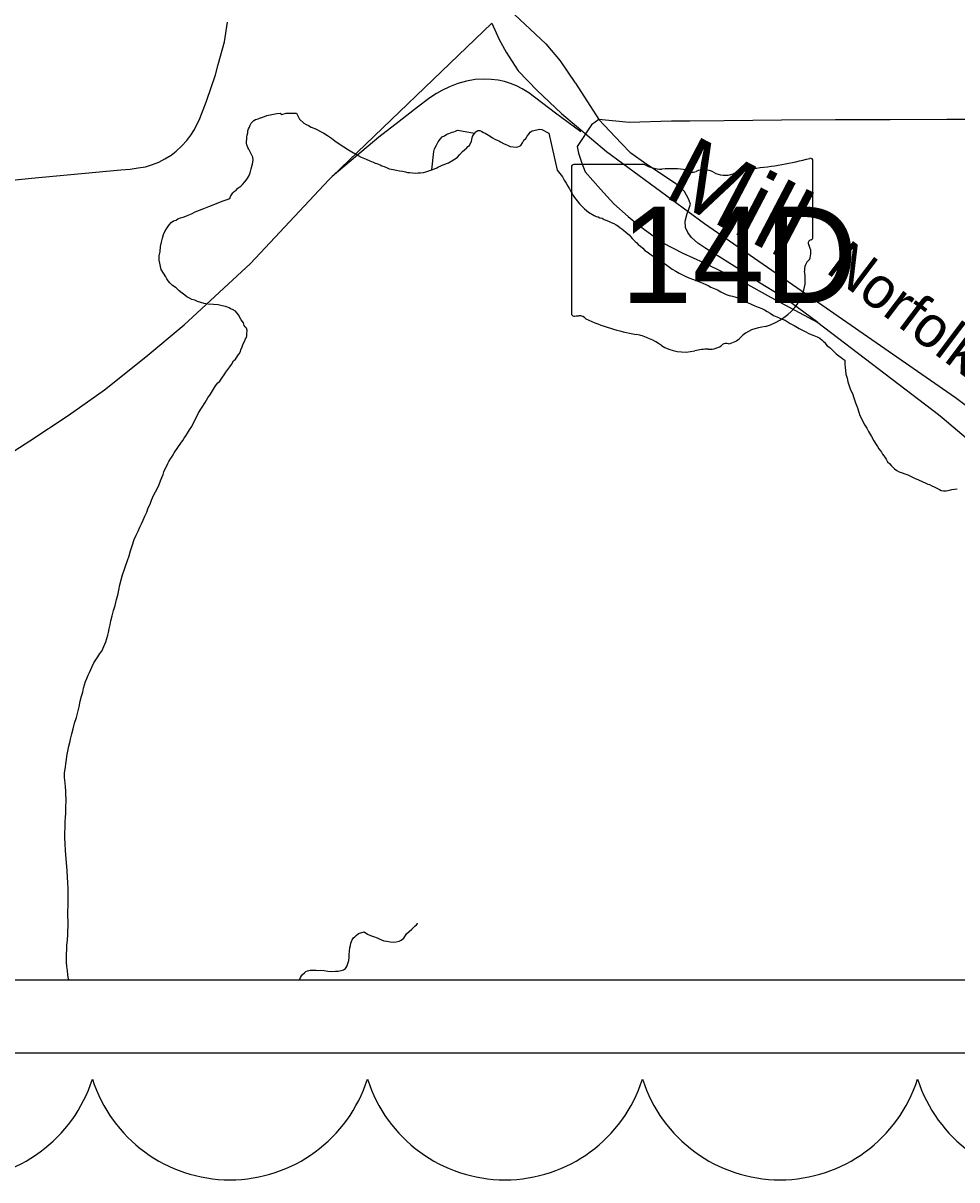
# Model space of a CAD drawing. Extents: x 0 to 96.2, y -27.5 to 31.3.
# Drawn here: x 48.919 to 50.194, y 13.714 to 15.293 of the extents above; entities that cross this region are included whole.
import ezdxf

# ---------------------------------------------------------------- set-up
doc = ezdxf.new("R2010")
doc.units = 0
for name, color, linetype in [('BOTTOM-BLKS', 7, 'Continuous'), ('TB1', 7, 'Continuous'), ('TB_BORDER', 7, 'Continuous'), ('TB_DUAL_PROF', 7, 'Continuous'), ('TB_PP_50x10_GRID', 7, 'Continuous'), ('TB_PROF_20x5', 7, 'Continuous'), ('TB_PROF_30x10', 7, 'Continuous'), ('TB_PSDSOD', 7, 'Continuous'), ('TB_SUPER_50x1_GRID', 7, 'Continuous')]:
    doc.layers.add(name, color=color, linetype=linetype)

msp = doc.modelspace()

# ---------------------------------------------------------------- linework, layer by layer
at = {"layer": 'BOTTOM-BLKS'}
msp.add_lwpolyline([(43.8234, 18.3711), (43.8234, 13.9869), (50.6234, 13.9869), (50.6234, 20.7869), (47.5697, 20.7869)], dxfattribs=at)
at = {"layer": 'TB1'}
for p, q in [((43.8234, 13.9869), (50.6234, 13.9869)), ((43.7234, 13.8869), (50.7234, 13.8869))]:
    msp.add_line(p, q, dxfattribs=at)
at = {"layer": 'TB_BORDER'}
for points in [[(49.1067, 14.9878), (49.1081, 14.9939), (49.1092, 14.9992), (49.1107, 15.0042), (49.1125, 15.0084), (49.1147, 15.0122), (49.1166, 15.0149), (49.1188, 15.0179), (49.1214, 15.0206), (49.1244, 15.0229), (49.1278, 15.0241), (49.1305, 15.0257), (49.1339, 15.0272), (49.1377, 15.028), (49.1411, 15.0292), (49.1445, 15.0308), (49.149, 15.0327), (49.1539, 15.0351), (49.1599, 15.0374), (49.166, 15.0398), (49.1728, 15.0425), (49.183, 15.0468), (49.1909, 15.05), (49.1977, 15.0523), (49.2011, 15.0535), (49.2022, 15.0562), (49.2037, 15.0585), (49.2052, 15.0612), (49.2074, 15.0631), (49.2101, 15.065), (49.2123, 15.0677), (49.2161, 15.0704), (49.2187, 15.0727), (49.2217, 15.0762), (49.225, 15.0804), (49.2273, 15.0839), (49.2291, 15.0884), (49.2305, 15.0938), (49.232, 15.1006), (49.233, 15.106), (49.2326, 15.1098), (49.2314, 15.1124), (49.2271, 15.1207), (49.226, 15.123), (49.2244, 15.1268), (49.224, 15.129), (49.2239, 15.1313), (49.2243, 15.1344), (49.2246, 15.1374), (49.225, 15.1401), (49.2257, 15.1431), (49.226, 15.1458), (49.2267, 15.1485), (49.2279, 15.1507), (49.229, 15.1534), (49.2304, 15.1561), (49.2323, 15.158), (49.2342, 15.1599), (49.2361, 15.1611), (49.2398, 15.1623), (49.2417, 15.1631), (49.2463, 15.1646), (49.2519, 15.1666), (49.2587, 15.1682), (49.2652, 15.1694), (49.2701, 15.1699), (49.2724, 15.168), (49.2781, 15.17), (49.2864, 15.1701), (49.2921, 15.1698), (49.2937, 15.1671), (49.2949, 15.1645), (49.2964, 15.1618), (49.3022, 15.1562), (49.3053, 15.1547), (49.3087, 15.1532), (49.3125, 15.151), (49.3171, 15.1492), (49.3209, 15.1473), (49.3251, 15.1451), (49.3297, 15.1425), (49.3347, 15.1395), (49.3401, 15.1358), (49.3447, 15.1324), (49.3504, 15.1283), (49.3569, 15.1238), (49.3631, 15.1197), (49.37, 15.1156), (49.3807, 15.11), (49.3872, 15.1071), (49.3925, 15.1048), (49.3971, 15.103), (49.3998, 15.1015), (49.4021, 15.1012), (49.4043, 15.1004), (49.4066, 15.0993), (49.4089, 15.0982), (49.412, 15.0971), (49.415, 15.096), (49.4189, 15.0941), (49.4242, 15.0931)], [(49.4242, 15.0931), (49.4288, 15.092), (49.4329, 15.0913), (49.4371, 15.0906), (49.4409, 15.0899), (49.444, 15.0891), (49.447, 15.0888), (49.4508, 15.0885), (49.455, 15.0881), (49.4584, 15.0885), (49.4615, 15.0886), (49.4656, 15.089), (49.469, 15.0898), (49.4728, 15.091), (49.477, 15.0926), (49.4808, 15.0938), (49.4838, 15.0953), (49.486, 15.0965), (49.4883, 15.0976), (49.4913, 15.0988), (49.494, 15.1), (49.497, 15.1012), (49.4996, 15.1023), (49.509, 15.1074), (49.512, 15.1101), (49.515, 15.1135), (49.5188, 15.1174), (49.5218, 15.1201), (49.5248, 15.1224), (49.5263, 15.1243), (49.5282, 15.1259), (49.5293, 15.1282), (49.5311, 15.1312), (49.5318, 15.1339), (49.5325, 15.1381), (49.534, 15.1404), (49.5355, 15.1427), (49.537, 15.1446), (49.54, 15.1465), (49.5423, 15.1462), (49.5454, 15.1451), (49.5473, 15.1436), (49.5496, 15.1425), (49.5522, 15.1414), (49.5542, 15.1399), (49.5568, 15.1384), (49.5599, 15.1365), (49.563, 15.1346), (49.566, 15.1332), (49.5683, 15.1321), (49.5706, 15.1306), (49.5748, 15.1287), (49.5779, 15.1272), (49.5805, 15.1261), (49.584, 15.1246), (49.5882, 15.1239), (49.5924, 15.1236), (49.5946, 15.124), (49.5965, 15.1248), (49.5984, 15.126), (49.6006, 15.1294), (49.6025, 15.1332), (49.6055, 15.1352), (49.6073, 15.1386), (49.6092, 15.1413), (49.6114, 15.144), (49.6141, 15.1459), (49.6243, 15.1483), (49.6273, 15.1476), (49.63, 15.1465), (49.6331, 15.1446), (49.6365, 15.1428), (49.6482, 15.0921)], [(49.4797, 15.1175), (49.4808, 15.1211), (49.4833, 15.1261), (49.4841, 15.128), (49.4856, 15.1307), (49.4871, 15.1326), (49.4889, 15.1349), (49.4912, 15.1376), (49.4942, 15.1391), (49.4976, 15.1411), (49.5002, 15.1423), (49.5025, 15.143), (49.5047, 15.1438), (49.507, 15.1446), (49.5093, 15.1454), (49.5119, 15.1466), (49.5355, 15.1427)], [(49.477, 15.0926), (49.4797, 15.1175)], [(49.6482, 15.0921), (49.6555, 15.0831), (49.6575, 15.0786), (49.6602, 15.0745), (49.6626, 15.0703), (49.6649, 15.0665), (49.6665, 15.0631), (49.6685, 15.0601), (49.67, 15.0575), (49.6716, 15.0548), (49.6735, 15.0526), (49.6755, 15.0503), (49.6786, 15.0462), (49.6805, 15.0443), (49.6825, 15.0421), (49.6852, 15.0394), (49.6879, 15.0372), (49.6909, 15.035), (49.6986, 15.0301), (49.7013, 15.029), (49.704, 15.0283), (49.7063, 15.0272), (49.7093, 15.0265), (49.712, 15.025), (49.7158, 15.0235), (49.7189, 15.022), (49.722, 15.0206), (49.7254, 15.0191), (49.7285, 15.0176), (49.7308, 15.0161), (49.7335, 15.0139), (49.7362, 15.012), (49.7385, 15.0102), (49.7416, 15.0075), (49.7443, 15.0053), (49.7462, 15.0038), (49.7485, 15.0012), (49.7505, 14.9989), (49.7528, 14.9967), (49.7547, 14.9948), (49.7567, 14.9929), (49.7586, 14.9907), (49.7617, 14.9884), (49.7648, 14.9858), (49.7679, 14.9824), (49.7721, 14.9798), (49.7752, 14.9776), (49.7786, 14.975), (49.7821, 14.9724), (49.7856, 14.9705), (49.7886, 14.9687), (49.7913, 14.9668), (49.7944, 14.9649), (49.7979, 14.9623), (49.8013, 14.9597), (49.8052, 14.9571), (49.8102, 14.9541), (49.8144, 14.9515), (49.8182, 14.9497), (49.8228, 14.9475), (49.8278, 14.9453), (49.8328, 14.9434), (49.8378, 14.9416), (49.8424, 14.9398), (49.8469, 14.9379), (49.8508, 14.9361), (49.8542, 14.9346), (49.8577, 14.9324), (49.8669, 14.9287), (49.8692, 14.9276), (49.8715, 14.9261), (49.8749, 14.9243), (49.8788, 14.9224), (49.883, 14.921), (49.8872, 14.9199), (49.8906, 14.9192), (49.8933, 14.9181), (49.8971, 14.9166), (49.9002, 14.9151), (49.9033, 14.9133), (49.9079, 14.9114), (49.9128, 14.9092), (49.9178, 14.907), (49.9224, 14.9052), (49.9274, 14.9033), (49.9312, 14.9015), (49.9347, 14.8993), (49.9389, 14.8971), (49.9435, 14.8937), (49.95, 14.8911), (49.9554, 14.8889), (49.9592, 14.8875), (49.9619, 14.8856), (49.9661, 14.883), (49.9715, 14.88), (49.9784, 14.8759), (49.9857, 14.8722), (49.9926, 14.8689)], [(49.0878, 14.625), (49.09, 14.6311), (49.0926, 14.6361), (49.0944, 14.6414), (49.097, 14.6479), (49.0999, 14.6529), (49.1025, 14.6582), (49.1047, 14.6628), (49.1065, 14.6682), (49.1084, 14.6727), (49.1102, 14.6766), (49.1113, 14.6804), (49.1132, 14.6846), (49.1146, 14.6876), (49.1165, 14.6915), (49.118, 14.6945), (49.1202, 14.698), (49.1217, 14.6999), (49.1239, 14.7037), (49.1254, 14.706), (49.1313, 14.7148), (49.1336, 14.7179), (49.1354, 14.7206), (49.1373, 14.7229), (49.1388, 14.7263), (49.1414, 14.7294), (49.1436, 14.7332), (49.1462, 14.7374), (49.1492, 14.742), (49.1518, 14.747), (49.1547, 14.7531), (49.1584, 14.7608), (49.1633, 14.7684), (49.1677, 14.7749), (49.1714, 14.7811), (49.1748, 14.7864), (49.1789, 14.7933), (49.1818, 14.7979), (49.1848, 14.8017), (49.1874, 14.8041), (49.1893, 14.8067), (49.1912, 14.8094), (49.1934, 14.8129), (49.196, 14.8163), (49.1986, 14.8201), (49.2012, 14.8236), (49.2035, 14.8267), (49.2061, 14.8316), (49.2091, 14.8343), (49.2109, 14.837), (49.2124, 14.8393), (49.2139, 14.8412), (49.2157, 14.8447), (49.2165, 14.847), (49.2179, 14.8508), (49.2194, 14.855), (49.2213, 14.8584), (49.2227, 14.8619), (49.2238, 14.8638), (49.2246, 14.8661), (49.2245, 14.8687), (49.2248, 14.8733), (49.224, 14.8763), (49.2221, 14.8782), (49.221, 14.8801), (49.2201, 14.8835), (49.2167, 14.8876), (49.2132, 14.8948), (49.2089, 14.8997), (49.2051, 14.9019), (49.2024, 14.903), (49.2005, 14.9042), (49.1982, 14.9053), (49.1952, 14.906), (49.1906, 14.9071), (49.1853, 14.9082), (49.1792, 14.9088), (49.1712, 14.9091), (49.1662, 14.9102), (49.1617, 14.9113), (49.1571, 14.9128), (49.1533, 14.9146), (49.1495, 14.9157), (49.146, 14.9172), (49.1426, 14.919), (49.1399, 14.9217), (49.1361, 14.9243), (49.1322, 14.9273), (49.128, 14.9314), (49.123, 14.9348), (49.1199, 14.9378), (49.1172, 14.9412), (49.1153, 14.9438), (49.1137, 14.9464), (49.1075, 14.9566), (49.1067, 14.9608), (49.1055, 14.9653), (49.1047, 14.9691), (49.105, 14.9752), (49.106, 14.9813), (49.1067, 14.9878)], [(49.9926, 14.8689), (49.9984, 14.8663), (50.003, 14.8645), (50.0068, 14.8627), (50.0099, 14.86), (50.0114, 14.8582), (50.0133, 14.8567), (50.0149, 14.8548), (50.0168, 14.8525), (50.0191, 14.851), (50.0211, 14.8492), (50.023, 14.8473), (50.0257, 14.8447), (50.0288, 14.8413), (50.0327, 14.8387), (50.0357, 14.8365), (50.0381, 14.8346), (50.0407, 14.8327), (50.0408, 14.827), (50.0413, 14.8232), (50.0422, 14.8137), (50.0438, 14.808), (50.045, 14.8031), (50.0466, 14.7978), (50.0486, 14.7921), (50.051, 14.7872), (50.053, 14.7812), (50.0554, 14.7743), (50.0578, 14.7675), (50.0598, 14.7618), (50.0614, 14.7573), (50.0633, 14.7531), (50.0653, 14.749), (50.0681, 14.7441), (50.0708, 14.7399), (50.0731, 14.7354), (50.0771, 14.7286), (50.0802, 14.7226), (50.0833, 14.7177), (50.0853, 14.7147), (50.0872, 14.7116), (50.0892, 14.709), (50.0907, 14.7071), (50.0923, 14.7045), (50.0938, 14.7022), (50.0954, 14.7003), (50.0973, 14.6977), (50.0989, 14.6939), (50.102, 14.6913), (50.104, 14.6891), (50.1059, 14.6872), (50.1086, 14.6846), (50.1117, 14.6819), (50.1151, 14.6805), (50.1189, 14.679), (50.1228, 14.6775), (50.1266, 14.6761), (50.1312, 14.6739), (50.1358, 14.6716), (50.1415, 14.6694), (50.1515, 14.665), (50.1542, 14.6635), (50.1565, 14.6628), (50.1596, 14.6613), (50.1626, 14.6599), (50.1653, 14.6584), (50.1672, 14.6573), (50.1699, 14.6562), (50.1722, 14.6547), (50.1756, 14.6543), (50.1791, 14.6544), (50.1813, 14.6548), (50.1836, 14.6552), (50.1866, 14.656), (50.1904, 14.6565), (50.1942, 14.6569)], [(48.9785, 14.016), (48.9784, 14.0221), (48.9787, 14.0282), (48.979, 14.0339), (48.9796, 14.0407), (48.9803, 14.0487), (48.9802, 14.054), (48.9805, 14.0593), (48.9805, 14.0639), (48.9804, 14.0681), (48.9803, 14.0723), (48.9803, 14.0764), (48.9802, 14.0814), (48.9805, 14.0867), (48.9805, 14.0924), (48.9808, 14.0977), (48.9807, 14.1053), (48.9806, 14.1118), (48.9801, 14.119), (48.9796, 14.127), (48.9791, 14.1357), (48.9768, 14.1634), (48.9763, 14.1725), (48.9762, 14.1809), (48.9761, 14.1881), (48.9764, 14.1942), (48.9767, 14.2026), (48.977, 14.2087), (48.9773, 14.2136), (48.9772, 14.2189), (48.9775, 14.2242), (48.9778, 14.2296), (48.9777, 14.2345), (48.9773, 14.2391), (48.9772, 14.2444), (48.9768, 14.2501), (48.9763, 14.2558), (48.9758, 14.263), (48.9758, 14.2683), (48.9761, 14.2725), (48.9768, 14.2767), (48.9775, 14.282), (48.9782, 14.287), (48.9788, 14.2919), (48.9795, 14.2965), (48.9806, 14.3011), (48.9817, 14.3056), (48.9828, 14.3106), (48.9838, 14.3152), (48.9856, 14.3224), (48.9874, 14.3296), (48.9892, 14.3373), (48.9918, 14.3449), (48.9936, 14.3521), (48.9954, 14.3594), (48.9972, 14.3674), (48.999, 14.3742), (49.0004, 14.3796), (49.0015, 14.3849), (49.0029, 14.3895), (49.0044, 14.3941), (49.0062, 14.3979), (49.0077, 14.4025), (49.0095, 14.4063), (49.0114, 14.4105), (49.0132, 14.4147), (49.0158, 14.4193), (49.0184, 14.4235), (49.021, 14.4277), (49.024, 14.4323), (49.0266, 14.4354), (49.0321, 14.4484), (49.0336, 14.4529), (49.0347, 14.4571), (49.0357, 14.461), (49.0364, 14.4659), (49.0379, 14.4712), (49.0389, 14.477), (49.0407, 14.4838), (49.0425, 14.4911), (49.0447, 14.4979), (49.0465, 14.5059), (49.0483, 14.512), (49.0498, 14.5189), (49.0512, 14.5261), (49.053, 14.533), (49.0548, 14.5395), (49.057, 14.546), (49.0592, 14.5528), (49.0617, 14.5593), (49.0639, 14.5658), (49.0657, 14.5723), (49.0679, 14.5792), (49.0708, 14.5879), (49.0734, 14.594), (49.076, 14.5994), (49.0786, 14.6047), (49.0808, 14.6093), (49.083, 14.6143), (49.0852, 14.6196), (49.0878, 14.625)], [(49.3624, 14.0092), (49.3635, 14.013), (49.3642, 14.0172), (49.3642, 14.0214), (49.3645, 14.026), (49.3652, 14.0302), (49.3659, 14.0336), (49.3666, 14.0366), (49.3673, 14.0389), (49.3684, 14.0412), (49.3699, 14.0439), (49.3718, 14.0454), (49.3737, 14.0474), (49.377, 14.0501), (49.3846, 14.0521), (49.3892, 14.0491), (49.3934, 14.0472), (49.3972, 14.0458), (49.4022, 14.0439), (49.4052, 14.0428), (49.4083, 14.0413), (49.4117, 14.0402), (49.4155, 14.0395), (49.4201, 14.0384), (49.4247, 14.0381), (49.4285, 14.0385), (49.4323, 14.0393), (49.4353, 14.0409), (49.4386, 14.0436), (49.4424, 14.0497), (49.4495, 14.0559), (49.454, 14.0601), (49.4562, 14.062), (49.4574, 14.0636), (49.4581, 14.0636)], [(48.9814, 13.9869), (48.9811, 13.9879), (48.9803, 13.9932), (48.9795, 13.9993), (48.979, 14.005), (48.9785, 14.0107), (48.9785, 14.016)], [(49.2963, 13.9869), (49.2967, 13.9875), (49.2978, 13.9898), (49.2992, 13.9921), (49.3004, 13.994), (49.303, 13.9964), (49.3052, 13.9979), (49.3075, 13.9991), (49.3109, 13.9999), (49.3162, 13.9999), (49.3193, 14), (49.3223, 13.9996), (49.3257, 13.9997), (49.3299, 13.9993), (49.3352, 13.9986), (49.3405, 13.9983), (49.3455, 13.9984), (49.3493, 13.9984), (49.3531, 13.9996), (49.3565, 14.0004), (49.3591, 14.0023), (49.361, 14.005), (49.3624, 14.0092)]]:
    msp.add_lwpolyline(points, dxfattribs=at)
at = {"layer": 'TB_DUAL_PROF'}
for p, q in [((49.7674, 15.1), (49.6709, 15.1)), ((49.9972, 15.0003), (49.9972, 15.105)), ((49.6676, 15.0966), (49.6676, 14.8964)), ((49.9972, 15.0003), (49.9972, 15.0003))]:
    msp.add_line(p, q, dxfattribs=at)
for centre, major_axis, start_param, end_param in [((49.6714, 15.097), (0.00382, 0), 1.712693, 3.28349), ((49.7904, 15.1232), (0.037, 0), 4.042523, 4.731795), ((49.8798, 15.3728), (0.3495, 0), 4.814394, 5.042369), ((49.9936, 15.1054), (0.00367, 0), 6.141152, 7.989035), ((49.8027, 14.9877), (0.133, 0), 1.404758, 1.657858), ((49.8329, 15.098), (0.0107, 0), 3.836095, 5.185415), ((49.8485, 15.0749), (0.0222, 0), 0.950623, 2.079405), ((49.8772, 15.1066), (0.0267, 0), 4.081561, 5.145723), ((49.9244, 15.0389), (0.0703, 0), 1.699011, 2.107814), ((49.9964, 14.9926), (0.00568, 0), 1.883978, 3.671073), ((49.9603, 14.9794), (0.0341, 0), 5.934695, 6.695948), ((49.9933, 14.9999), (0.00393, 0), 5.05454, 6.418171), ((50.0104, 14.9565), (0.0248, 0), 2.387724, 3.262537), ((49.8994, 14.9432), (0.0874, 0), 5.101752, 6.440018), ((49.6715, 14.896), (0.00385, 0), 3.00124, 4.508301), ((49.672, 14.9165), (0.0294, 0), 4.665946, 4.897461), ((49.6781, 14.8849), (0.0106, 0), 0.519207, 1.627899), ((49.8119, 15.0647), (0.2524, 0), 4.195997, 4.488961), ((49.9363, 14.8403), (0.0479, 0), 1.647645, 2.488434), ((49.7366, 14.8065), (0.079, 0), 0.823519, 1.323587), ((49.8756, 14.877), (0.0282, 0), 4.937069, 5.64225), ((49.822, 14.8839), (0.0501, 0), 4.026481, 4.996735), ((49.851, 14.8147), (0.0412, 0), 1.495662, 1.94098), ((49.8547, 14.8689), (0.0267, 0), 4.691044, 5.507374), ((49.8788, 14.8495), (0.00752, 0), 1.147584, 2.315152)]:
    msp.add_ellipse(centre, major_axis=major_axis, ratio=0.8, start_param=start_param, end_param=end_param, dxfattribs=at)
at = {"layer": 'TB_PP_50x10_GRID'}
for points in [[(48.7452, 15.062), (48.9304, 15.0814), (49.0185, 15.0892), (49.0527, 15.0924), (49.0653, 15.0937), (49.0762, 15.0952), (49.086, 15.0967), (49.0958, 15.0997), (49.1042, 15.1032), (49.1126, 15.1074), (49.1212, 15.1128), (49.1282, 15.1182), (49.1358, 15.1252), (49.1425, 15.1325), (49.1482, 15.1399), (49.153, 15.1478), (49.1601, 15.1628), (49.1696, 15.1862), (49.1816, 15.2225), (49.1855, 15.2365), (49.1939, 15.2675), (49.1982, 15.2942)], [(49.3408, 15.0834), (49.5587, 15.2929)], [(49.5587, 15.2929), (49.5689, 15.2706), (49.5783, 15.2533), (49.595, 15.2277), (49.6207, 15.2011), (49.6542, 15.1695), (49.7154, 15.1177), (49.849, 15.0195), (50.1917, 14.7818), (50.6234, 14.4573)], [(49.6805, 15.1446), (49.6459, 15.1698), (49.6092, 15.1979), (49.6004, 15.2034), (49.5926, 15.2073), (49.5842, 15.2104), (49.5761, 15.2132), (49.5675, 15.2149), (49.5581, 15.2159), (49.5471, 15.2164), (49.5361, 15.2158), (49.5242, 15.2138), (49.5125, 15.2105), (49.5009, 15.206), (49.4908, 15.201), (49.4833, 15.1967), (49.4744, 15.1908), (49.4573, 15.178), (49.4324, 15.1587), (49.4047, 15.137), (49.3408, 15.0834)], [(49.1444, 14.8859), (49.2293, 14.9646), (49.3365, 15.0788), (49.3408, 15.0834)], [(48.6746, 14.5706), (48.7423, 14.6099), (48.8726, 14.6872), (48.9284, 14.7226), (48.9806, 14.7574), (49.0304, 14.7923), (49.0865, 14.8373), (49.1389, 14.8808), (49.1444, 14.8859)]]:
    msp.add_lwpolyline(points, dxfattribs=at)
at = {"layer": 'TB_PSDSOD'}
for points in [[(48.9256, 16.0453), (48.9613, 16.0058), (48.9943, 15.9681), (49.0388, 15.919), (49.0814, 15.8724), (49.129, 15.819), (49.1686, 15.775), (49.2081, 15.7318), (49.2147, 15.7243), (49.2526, 15.6811), (49.3002, 15.6281), (49.3444, 15.5792), (49.3916, 15.527), (49.4338, 15.4796), (49.4632, 15.4461), (49.4711, 15.4372), (49.496, 15.4093), (49.5494, 15.3496), (49.5531, 15.3453), (49.5832, 15.3109), (49.6327, 15.2644), (49.6522, 15.2416), (49.6724, 15.212), (49.673, 15.2109)], [(49.673, 15.2109), (49.7049, 15.1611)], [(49.7049, 15.1611), (49.6949, 15.154), (49.6753, 15.1243)], [(50.6234, 15.1671), (50.6187, 15.167), (50.5428, 15.1654), (50.465, 15.1645), (50.3955, 15.1638), (50.3378, 15.1629), (50.293, 15.1633), (50.2437, 15.1614), (50.18, 15.1615), (50.1025, 15.161), (50.0281, 15.161), (49.9541, 15.1605), (49.876, 15.1593), (49.8292, 15.159), (49.8042, 15.1589), (49.7462, 15.1571), (49.7049, 15.1611)], [(49.8272, 15.0374), (49.8299, 15.0455), (49.8274, 15.0529), (49.8218, 15.063), (49.8145, 15.0701), (49.8068, 15.0757), (49.7692, 15.101), (49.7487, 15.1153), (49.7354, 15.1292), (49.7049, 15.1611)], [(49.6753, 15.1243), (49.6773, 15.1155), (49.6818, 15.1017), (49.6863, 15.0898), (49.7071, 15.0661), (49.7255, 15.0461), (49.7448, 15.0288), (49.7585, 15.0177), (49.7843, 14.9988), (49.7923, 14.993), (49.8198, 14.9786), (49.8478, 14.9662), (49.8765, 14.9518), (49.9044, 14.9382), (49.9404, 14.9182), (50.0038, 14.8842)], [(50.0038, 14.8842), (49.9675, 14.9111), (49.9518, 14.9214), (49.9253, 14.9378), (49.8984, 14.9556), (49.8723, 14.9719), (49.8512, 14.9852), (49.8401, 14.9926), (49.8316, 15.0001), (49.8266, 15.0072), (49.8234, 15.014), (49.8229, 15.0224), (49.8257, 15.0331), (49.8272, 15.0374)], [(50.0038, 14.8842), (50.1684, 14.7584)], [(50.1684, 14.7584), (50.1737, 14.7543), (50.5777, 14.4118), (50.5916, 14.4004), (50.6096, 14.3899), (50.6234, 14.3837)]]:
    msp.add_lwpolyline(points, dxfattribs=at)
at = {"layer": 'TB_SUPER_50x1_GRID'}
for centre in [(48.826, 13.9105), (49.2014, 13.9105), (49.5769, 13.9105), (49.9523, 13.9105), (50.3278, 13.9105)]:
    msp.add_arc(centre, 0.1968, 197.5, 342.5, dxfattribs=at)

# ---------------------------------------------------------------- texts
at = {"layer": 'TB_DUAL_PROF'}
msp.add_text('14D', height=0.13184, dxfattribs=at).set_placement((49.7347, 14.9106))
at = {"layer": 'TB_PROF_20x5'}
msp.add_text('Norfolk Southern', height=0.056629, rotation=323.0651, dxfattribs=at).set_placement((50.0129, 14.9538))
at = {"layer": 'TB_PROF_30x10'}
msp.add_text('Mill', height=0.09476, rotation=332.3915, dxfattribs=at).set_placement((49.7915, 15.057))

doc.saveas('drawing.dxf')
